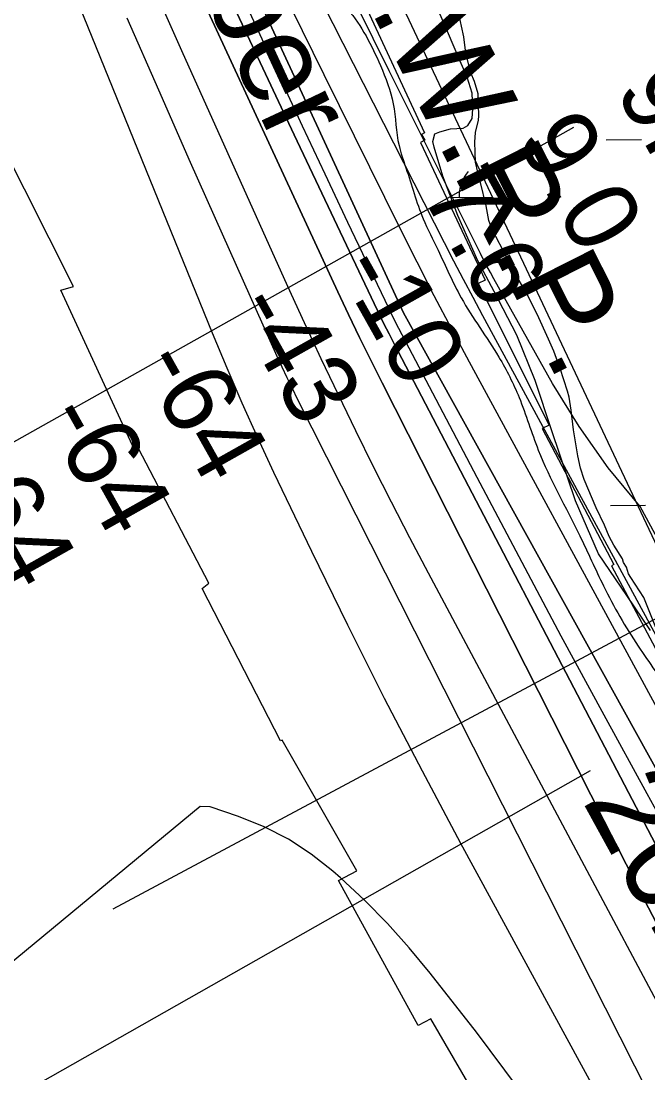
# Model space of a CAD drawing. Extents: x 3684037 to 3722149, y 433263 to 459021.
# Drawn here: x 3711812 to 3712383, y 439267 to 440224 of the extents above; entities that cross this region are included whole.
import ezdxf

# ---------------------------------------------------------------- set-up
doc = ezdxf.new("R2010")
doc.units = 0
for name, color, linetype in [('V-RIVR-EDGE', 7, 'Continuous'), ('V-RIVR-IDEN', 7, 'Continuous'), ('V-RIVR-RANG', 7, 'Continuous'), ('V-RRAP-DIKE', 7, 'Continuous'), ('V-RRAP-FSHR', 7, 'Continuous'), ('V-RRAP-RVMT', 7, 'Continuous'), ('V-SITE-VEGE', 7, 'Continuous'), ('V-TOPO-DPTH', 7, 'Continuous'), ('V-TOPO-MAJR', 7, 'Continuous'), ('V-TOPO-MINR', 7, 'Continuous'), ('V-TOPO-WATR', 7, 'Continuous'), ('V-TOPO-WATR-IDEN', 7, 'Continuous'), ('V-WETL-SWMP', 7, 'Continuous')]:
    doc.layers.add(name, color=color, linetype=linetype)

msp = doc.modelspace()

# ---------------------------------------------------------------- linework, layer by layer
at = {"layer": 'V-RIVR-EDGE'}
msp.add_spline([(3710881.85, 442907.17), (3710900.3, 442872.76), (3710912.89, 442844.25), (3710926.84, 442815.27), (3710939.89, 442789.92), (3710950.22, 442762.31), (3710961.88, 442723.85), (3710972.69, 442706.64), (3710987.55, 442681.29), (3711004.19, 442645.52), (3711013.15, 442612.95), (3711017.62, 442590.33), (3711028.39, 442559.55), (3711043.23, 442525.61), (3711061.24, 442493.46), (3711083.32, 442464.01), (3711101.79, 442435.48), (3711123.37, 442385.69), (3711146.29, 442329.57), (3711160.2, 442285.22), (3711177.71, 442238.15), (3711205.6, 442178.4), (3711227.63, 442127.25), (3711258.71, 442079.24), (3711273.08, 442038.51), (3711277.08, 442009.57), (3711279.27, 441982.43), (3711285.11, 441965.69), (3711299.53, 441946.66), (3711314.4, 441925.82), (3711322.93, 441901.39), (3711344.09, 441864.26), (3711361.61, 441818.09), (3711381.38, 441766.05), (3711387.6, 441724.88), (3711408.3, 441685.04), (3711430.33, 441634.35), (3711446.97, 441597.23), (3711483.42, 441524.79), (3711505.9, 441474.1), (3711521.64, 441439.69), (3711545.49, 441393.97), (3711577.41, 441319.28), (3711605.29, 441255.01), (3711666.49, 441137.74), (3711693.94, 441084.32), (3711722.25, 441011.45), (3711736.18, 440977.51), (3711773.54, 440908.24), (3711800.07, 440850.29), (3711813.99, 440812.28), (3711827.94, 440785.11), (3711836.49, 440767.46), (3711872.07, 440711.3), (3711903.57, 440647.92), (3711936.4, 440576.4), (3711963.82, 440513.48), (3711991.74, 440467.29), (3712009.3, 440437.41), (3712020.05, 440394.43), (3712026.76, 440365.47), (3712043.42, 440336.04), (3712066.37, 440292.58), (3712088.89, 440257.25), (3712109.18, 440235.05), (3712138.9, 440183.88), (3712150.57, 440149.03), (3712155.9, 440111.04), (3712162.18, 440090.68), (3712177.89, 440044.52), (3712191.39, 440016), (3712212.53, 439972.54), (3712246.76, 439918.65), (3712265.21, 439881.98), (3712282.72, 439834), (3712320.51, 439756.14), (3712342.1, 439710.42), (3712373.62, 439655.63), (3712403.35, 439610.34), (3712425.83, 439558.28), (3712451.47, 439505.77), (3712470.39, 439476.33), (3712503.75, 439435.1), (3712518.6, 439408.84), (3712544.23, 439350.45), (3712559.09, 439322.83), (3712605.51, 439263.94), (3712623.98, 439233.6), (3712641.51, 439193.31), (3712662.18, 439142.17), (3712689.17, 439086.03), (3712722.5, 439033.5), (3712753.58, 438981.88), (3712765.15, 438962.6)], degree=3, dxfattribs=at)
at = {"layer": 'V-RIVR-RANG'}
msp.add_line((3712724.5, 439859.46), (3711895.41, 439416.5), dxfattribs=at)
at = {"layer": 'V-RRAP-DIKE'}
for p, q in [((3712314.9, 440127.6), (3710217.76, 438950.24)), ((3712330, 439542.4), (3711302.42, 438960.06))]:
    msp.add_line(p, q, dxfattribs=at)
at = {"layer": 'V-RRAP-FSHR'}
msp.add_lwpolyline([(3710449.88, 443948.54), (3711032.4, 442732.84), (3711461.51, 441700.35), (3711800.31, 440955.81), (3712037.99, 440494.59), (3712458, 439603.75), (3712696.92, 439205.07), (3712836.7, 438963.43)], dxfattribs=at)
at = {"layer": 'V-RRAP-RVMT'}
for p, q in [((3712126.88, 440234.82), (3712178.95, 440122.56)), ((3712178.95, 440122.56), (3712176.48, 440121.12)), ((3712176.48, 440121.12), (3712179.37, 440115.83)), ((3711859.54, 439982.7), (3711792.51, 440115.34)), ((3712179.37, 440115.83), (3712175.5, 440113.66)), ((3712175.5, 440113.66), (3712234.43, 439988.49)), ((3712234.43, 439988.49), (3712227.99, 439985.56)), ((3711847.82, 439979.36), (3711859.54, 439982.7)), ((3711915.05, 439834.38), (3711847.82, 439979.36)), ((3712227.99, 439985.56), (3712292.46, 439856.81)), ((3712292.46, 439856.81), (3712286.2, 439853.69)), ((3712286.2, 439853.69), (3712351.52, 439729.9)), ((3711918.56, 439835.54), (3711915.05, 439834.38)), ((3711982.58, 439712.84), (3711918.56, 439835.54)), ((3712351.52, 439729.9), (3712349.23, 439728.84)), ((3712349.23, 439728.84), (3712416.17, 439603.02)), ((3711976.69, 439708), (3711982.58, 439712.84)), ((3712048.03, 439569.4), (3711976.69, 439708)), ((3712049.6, 439570.17), (3712048.03, 439569.4)), ((3712117.38, 439451.16), (3712049.6, 439570.17)), ((3712100.91, 439442.35), (3712117.38, 439451.16)), ((3712173.39, 439310.47), (3712100.91, 439442.35)), ((3712184.98, 439316.71), (3712173.39, 439310.47)), ((3712258.34, 439190.39), (3712184.98, 439316.71))]:
    msp.add_line(p, q, dxfattribs=at)
at = {"layer": 'V-SITE-VEGE'}
for p, q in [((3712212.91, 440219.73), (3712209.02, 440236.55)), ((3712214.86, 440209.91), (3712212.91, 440219.73)), ((3712216.86, 440194.95), (3712214.86, 440209.91)), ((3712221.22, 440177.19), (3712216.86, 440194.95)), ((3712224.56, 440169.26), (3712221.22, 440177.19)), ((3712227.93, 440158.05), (3712224.56, 440169.26)), ((3712228.56, 440137.93), (3712227.93, 440158.05)), ((3712225.41, 440122.92), (3712228.13, 440134.18)), ((3712228.13, 440134.18), (3712228.56, 440137.93)), ((3712225.02, 440114.02), (3712225.41, 440122.92)), ((3712225.64, 440095.77), (3712225.02, 440114.02)), ((3712227.58, 440086.89), (3712225.64, 440095.77)), ((3712230, 440077.54), (3712227.58, 440086.89)), ((3712235.33, 440056.06), (3712230, 440077.54)), ((3712237.77, 440042.97), (3712235.33, 440056.06)), ((3712240.65, 440034.56), (3712237.77, 440042.97)), ((3712254.45, 440008.46), (3712240.65, 440034.56)), ((3712264.43, 439989.82), (3712254.45, 440008.46)), ((3712271.56, 439977.23), (3712264.43, 439989.82)), ((3712281.55, 439957.66), (3712271.56, 439977.23)), ((3712292.04, 439934.8), (3712281.55, 439957.66)), ((3712296.81, 439924.07), (3712292.04, 439934.8)), ((3712302.56, 439908.2), (3712296.81, 439924.07)), ((3712309.28, 439887.66), (3712302.56, 439908.2)), ((3712310.73, 439882.05), (3712309.28, 439887.66)), ((3712312.7, 439870.37), (3712310.73, 439882.05)), ((3712314.72, 439852.59), (3712312.7, 439870.37)), ((3712318.66, 439828.75), (3712314.72, 439852.59)), ((3712321.09, 439817.53), (3712318.66, 439828.75)), ((3712324.46, 439807.26), (3712321.09, 439817.53)), ((3712335.44, 439781.6), (3712324.46, 439807.26)), ((3712343.06, 439765.75), (3712335.44, 439781.6)), ((3712347.35, 439755.49), (3712343.06, 439765.75)), ((3712351.63, 439747.56), (3712347.35, 439755.49)), ((3712359.23, 439734.99), (3712351.63, 439747.56)), ((3712360.19, 439731.72), (3712359.23, 439734.99)), ((3712363.03, 439727.53), (3712360.19, 439731.72)), ((3712364.96, 439721.46), (3712363.03, 439727.53)), ((3712366.86, 439718.19), (3712364.96, 439721.46)), ((3712378.71, 439700.03), (3712366.86, 439718.19)), ((3712392.1, 439666.44), (3712378.71, 439700.03))]:
    msp.add_line(p, q, dxfattribs=at)
at = {"layer": 'V-TOPO-DPTH'}
for points in [[(3712711.91, 438961.98), (3712683.26, 439014.44), (3712669.9, 439038.84), (3712656.51, 439063.23), (3712643.07, 439087.58), (3712629.6, 439111.92), (3712159.9, 439958.74), (3711790.59, 440757.32)], [(3711790.59, 440757.32), (3712159.9, 439958.74), (3712629.6, 439111.92), (3712643.07, 439087.58), (3712656.51, 439063.23), (3712669.9, 439038.84), (3712683.26, 439014.44), (3712711.91, 438961.98)], [(3712775.94, 438962.72), (3712772.45, 438970), (3712768.37, 438979.09), (3712764.64, 438988.33), (3712761.15, 438997.67), (3712756.93, 439009.65), (3712755.87, 439013.11), (3712755, 439016.6), (3712754.42, 439020.15), (3712754.04, 439023.75), (3712753.61, 439027.32), (3712752.94, 439030.84), (3712751.9, 439034.26), (3712599.91, 439279.32), (3712589.26, 439298.44), (3712232.32, 439956.11), (3712223.41, 439972.67), (3712214.6, 439989.28), (3712205.92, 440005.96), (3712197.32, 440022.68), (3711902.32, 440602.62)], [(3712630.61, 438961.03), (3712603, 439008.9), (3712598.54, 439016.71), (3712594.12, 439024.53), (3712589.75, 439032.38), (3712585.42, 439040.26), (3712508.55, 439181.19), (3712466.17, 439259.74), (3712424.26, 439338.53), (3712383.05, 439417.7), (3712342.32, 439497.11), (3712140.47, 439895.05), (3712130.14, 439915.69), (3712119.96, 439936.41), (3712109.99, 439957.23), (3712100.18, 439978.12), (3711852.57, 440512.66)], [(3711852.57, 440512.66), (3712100.18, 439978.12), (3712109.99, 439957.23), (3712119.96, 439936.41), (3712130.14, 439915.69), (3712140.47, 439895.05), (3712342.32, 439497.11), (3712383.05, 439417.7), (3712424.26, 439338.53), (3712466.17, 439259.74), (3712508.55, 439181.19), (3712585.42, 439040.26), (3712589.75, 439032.38), (3712594.12, 439024.53), (3712598.54, 439016.71), (3712603, 439008.9), (3712630.61, 438961.03)], [(3711979.56, 440292.74), (3712019.96, 440206.64), (3712060.55, 440120.63), (3712133.23, 439967.27), (3712137.67, 439958.03), (3712142.19, 439948.84), (3712146.81, 439939.69), (3712151.5, 439930.58), (3712386.11, 439482), (3712424.88, 439408.36), (3712463.91, 439334.85), (3712503.34, 439261.56), (3712543.03, 439188.41), (3712582.5, 439116.14), (3712602.71, 439079.27), (3712623, 439042.43), (3712643.4, 439005.66), (3712663.88, 438968.93), (3712666.87, 438963.6), (3712668.06, 438961.47)], [(3711979.56, 440292.74), (3712019.96, 440206.64), (3712060.55, 440120.63), (3712133.23, 439967.27), (3712137.67, 439958.03), (3712142.19, 439948.84), (3712146.81, 439939.69), (3712151.5, 439930.58), (3712386.11, 439482), (3712424.88, 439408.36), (3712463.91, 439334.85), (3712503.34, 439261.56), (3712543.03, 439188.41), (3712582.5, 439116.14), (3712602.71, 439079.27), (3712623, 439042.43), (3712643.4, 439005.66), (3712663.88, 438968.93), (3712666.87, 438963.6), (3712668.06, 438961.47)], [(3712590.85, 438960.57), (3712590.74, 438960.77), (3712577.83, 438983.59), (3712565.06, 439006.49), (3712552.48, 439029.5), (3712540.03, 439052.58), (3712182.61, 439722.15), (3712165.69, 439754.27), (3712148.99, 439786.51), (3712132.64, 439818.92), (3712116.52, 439851.46), (3712100.72, 439884.15), (3712085.12, 439916.94), (3712069.84, 439949.87), (3712054.75, 439982.89), (3712000.27, 440103.65), (3711958.26, 440197.2), (3711916.46, 440290.85)], [(3712590.85, 438960.57), (3712590.74, 438960.77), (3712577.83, 438983.59), (3712565.06, 439006.49), (3712552.48, 439029.5), (3712540.03, 439052.58), (3712182.61, 439722.15), (3712165.69, 439754.27), (3712148.99, 439786.51), (3712132.64, 439818.92), (3712116.52, 439851.46), (3712100.72, 439884.15), (3712085.12, 439916.94), (3712069.84, 439949.87), (3712054.75, 439982.89), (3712000.27, 440103.65), (3711958.26, 440197.2), (3711916.46, 440290.85)]]:
    msp.add_lwpolyline(points, dxfattribs=at)
at = {"layer": 'V-TOPO-MAJR'}
msp.add_lwpolyline([(3712532.73, 438959.89), (3712523.16, 438976.67), (3712522.35, 438978.1), (3712521.55, 438979.53), (3712520.76, 438980.97), (3712519.97, 438982.4), (3712506.6, 439007.03), (3712499.2, 439020.82), (3712491.87, 439034.65), (3712484.67, 439048.54), (3712477.54, 439062.47), (3712063.54, 439880.36), (3712058.76, 439889.97), (3712054.08, 439899.62), (3712049.53, 439909.34), (3712045.07, 439919.1), (3711995.22, 440030.28), (3711966.05, 440095.73), (3711937.09, 440161.27), (3711908.43, 440226.94)], dxfattribs=at)
at = {"layer": 'V-TOPO-MINR'}
for p, q in [((3711974.77, 439509.9), (3711541.05, 439151.73)), ((3711983.81, 439509.56), (3711974.77, 439509.9)), ((3712009.74, 439500.79), (3711983.81, 439509.56)), ((3712032.97, 439491.35), (3712009.74, 439500.79)), ((3712055.21, 439480.19), (3712032.97, 439491.35)), ((3712075.95, 439466.45), (3712055.21, 439480.19)), ((3712095.7, 439450.99), (3712075.95, 439466.45)), ((3712102.55, 439444.93), (3712095.7, 439450.99)), ((3712124.35, 439424.56), (3712102.55, 439444.93)), ((3712145.37, 439403.44), (3712124.35, 439424.56)), ((3712165.2, 439381.2), (3712145.37, 439403.44)), ((3712184.24, 439358.22), (3712165.2, 439381.2)), ((3712226.38, 439304.47), (3712184.24, 439358.22)), ((3712264.76, 439253.3), (3712226.38, 439304.47))]:
    msp.add_line(p, q, dxfattribs=at)
for points in [[(3712690.03, 438961.73), (3712670.77, 438996.58), (3712655.24, 439024.69), (3712639.72, 439052.81), (3712624.21, 439080.94), (3712608.71, 439109.07), (3712381.75, 439521.26), (3712342.55, 439592.95), (3712303.64, 439664.79), (3712265.15, 439736.86), (3712226.94, 439809.08), (3712155.72, 439944.67), (3712153.36, 439949.22), (3712151.04, 439953.79), (3712148.78, 439958.39), (3712146.55, 439963), (3712109.43, 440041.15), (3712088.74, 440084.88), (3712068.15, 440128.66), (3712047.7, 440172.51), (3712027.35, 440216.4), (3711775.13, 440762.6)], [(3712711.91, 438961.98), (3712683.26, 439014.44), (3712669.9, 439038.84), (3712656.51, 439063.23), (3712643.07, 439087.58), (3712629.6, 439111.92), (3712159.9, 439958.74), (3711790.59, 440757.32)], [(3712630.61, 438961.03), (3712603, 439008.9), (3712598.54, 439016.71), (3712594.12, 439024.53), (3712589.75, 439032.38), (3712585.42, 439040.26), (3712508.55, 439181.19), (3712466.17, 439259.74), (3712424.26, 439338.53), (3712383.05, 439417.7), (3712342.32, 439497.11), (3712140.47, 439895.05), (3712130.14, 439915.69), (3712119.96, 439936.41), (3712109.99, 439957.23), (3712100.18, 439978.12), (3711852.57, 440512.66)], [(3712494, 438959.44), (3712492.76, 438961.67), (3712483.75, 438977.99), (3712474.79, 438994.34), (3712212.29, 439476.14), (3712177.13, 439541.9), (3712142.67, 439608.01), (3712109.24, 439674.66), (3712076.51, 439741.66), (3712042.02, 439813.68), (3712027.34, 439845.06), (3712013.04, 439876.61), (3711999.32, 439908.42), (3711985.98, 439940.39), (3711834.89, 440312.03)], [(3712668.06, 438961.47), (3712666.87, 438963.6), (3712663.88, 438968.93), (3712643.4, 439005.66), (3712623, 439042.43), (3712602.71, 439079.27), (3712582.5, 439116.14), (3712543.03, 439188.41), (3712503.34, 439261.56), (3712463.91, 439334.85), (3712424.88, 439408.36), (3712386.11, 439482), (3712151.5, 439930.58), (3712146.81, 439939.69), (3712142.19, 439948.84), (3712137.67, 439958.03), (3712133.23, 439967.27), (3712060.55, 440120.63), (3712019.96, 440206.64), (3711979.56, 440292.74)], [(3712590.85, 438960.57), (3712590.74, 438960.77), (3712577.83, 438983.59), (3712565.06, 439006.49), (3712552.48, 439029.5), (3712540.03, 439052.58), (3712182.61, 439722.15), (3712165.69, 439754.27), (3712148.99, 439786.51), (3712132.64, 439818.92), (3712116.52, 439851.46), (3712100.72, 439884.15), (3712085.12, 439916.94), (3712069.84, 439949.87), (3712054.75, 439982.89), (3712000.27, 440103.65), (3711958.26, 440197.2), (3711916.46, 440290.85)], [(3712736.43, 438962.27), (3712712.94, 439006.14), (3712694.4, 439040.69), (3712675.81, 439075.2), (3712657.14, 439109.68), (3712638.42, 439144.12), (3712574.33, 439261.75), (3712523.55, 439355.01), (3712472.81, 439448.28), (3712422.11, 439541.59), (3712371.45, 439634.91), (3712220.08, 439913.93), (3712203.92, 439944.11), (3712187.99, 439974.41), (3712172.4, 440004.88), (3712157.04, 440035.47), (3712087.75, 440175.37), (3712038.19, 440276.14)], [(3712819.96, 438963.24), (3712375.6, 439782.6), (3712346.28, 439817.89), (3712320, 439855.5), (3712295.75, 439894.66), (3712242.22, 439989.76), (3712239.06, 439995.47), (3712235.95, 440001.21), (3712232.94, 440007), (3712229.97, 440012.81), (3712146.88, 440178.99), (3712102.85, 440268.13)]]:
    msp.add_lwpolyline(points, dxfattribs=at)
at = {"layer": 'V-TOPO-WATR'}
msp.add_lwpolyline([(3712775.94, 438962.72), (3712772.45, 438970), (3712768.37, 438979.09), (3712764.64, 438988.33), (3712761.15, 438997.67), (3712756.93, 439009.65), (3712755.87, 439013.11), (3712755, 439016.6), (3712754.42, 439020.15), (3712754.04, 439023.75), (3712753.61, 439027.32), (3712752.94, 439030.84), (3712751.9, 439034.26), (3712599.91, 439279.32), (3712589.26, 439298.44), (3712232.32, 439956.11), (3712223.41, 439972.67), (3712214.6, 439989.28), (3712205.92, 440005.96), (3712197.32, 440022.68), (3711902.32, 440602.62)], dxfattribs=at)
at = {"layer": 'V-WETL-SWMP'}
for p, q in [((3712201, 440212.65), (3712191.12, 440235.24)), ((3712210.3, 440190.64), (3712201, 440212.65)), ((3712217.85, 440173.26), (3712210.3, 440190.64)), ((3712222.51, 440158.78), (3712217.85, 440173.26)), ((3712223.1, 440144.29), (3712222.51, 440158.78)), ((3712222.53, 440135.6), (3712223.1, 440144.29)), ((3712218.49, 440129.22), (3712222.53, 440135.6)), ((3712186.63, 440114.69), (3712188.36, 440121.65)), ((3712188.36, 440121.65), (3712192.99, 440123.39)), ((3712192.99, 440123.39), (3712202.84, 440126.3)), ((3712202.84, 440126.3), (3712214.43, 440126.89)), ((3712214.43, 440126.89), (3712218.49, 440129.22)), ((3712187.79, 440109.47), (3712186.63, 440114.69)), ((3712344.56, 440116.14), (3712376.56, 440116.51)), ((3712195.81, 440083.04), (3712187.79, 440109.47)), ((3712209.35, 440047.29), (3712195.81, 440083.04)), ((3712203.12, 440063.75), (3712240.56, 440064.18)), ((3712227.62, 440006.13), (3712209.35, 440047.29)), ((3712242.66, 439978.19), (3712227.62, 440006.13)), ((3712263.25, 439938.61), (3712242.66, 439978.19)), ((3712279.96, 439897.43), (3712263.25, 439938.61)), ((3712295.15, 439851.57), (3712279.96, 439897.43)), ((3712316.72, 439787.83), (3712295.15, 439851.57)), ((3712337.38, 439739.67), (3712316.72, 439787.83)), ((3712348.43, 439783.48), (3712380.43, 439783.86)), ((3712363.42, 439701.69), (3712337.38, 439739.67)), ((3712384.72, 439669.9), (3712363.42, 439701.69))]:
    msp.add_line(p, q, dxfattribs=at)
msp.add_arc((3712245.8, 440064.72), 35.25, 139.89487, 181.43852, dxfattribs=at)

# ---------------------------------------------------------------- texts
at = {"layer": 'V-RIVR-IDEN'}
for s, rotation, p in [('September', 294.90477, (3711814.61, 440599.85)), ('2012', 298.80526, (3712322.27, 439515.01))]:
    msp.add_text(s, height=83, rotation=rotation, dxfattribs=at).set_placement(p)
at = {"layer": 'V-RIVR-RANG'}
for s, rotation, p in [('9.1', 299.03833, (3712352.2, 440161.4)), ('9.0', 299.03833, (3712262.33, 440117.25)), ('7.6', 299.03833, (3712175.54, 440067.57)), ('-10', 299.32358, (3712098.65, 439999.36)), ('-43', 299.32358, (3712003.47, 439964.64)), ('-64', 299.32358, (3711917.84, 439912.89)), ('-64', 299.32358, (3711830.53, 439864.13)), ('-64', 299.32358, (3711743.22, 439815.37))]:
    msp.add_text(s, height=67, rotation=rotation, dxfattribs=at).set_placement(p)
at = {"layer": 'V-TOPO-WATR-IDEN'}
msp.add_text('L.W.R.P.', height=83, rotation=296.79822, dxfattribs=at).set_placement((3712101.55, 440290.4))

doc.saveas('drawing.dxf')
